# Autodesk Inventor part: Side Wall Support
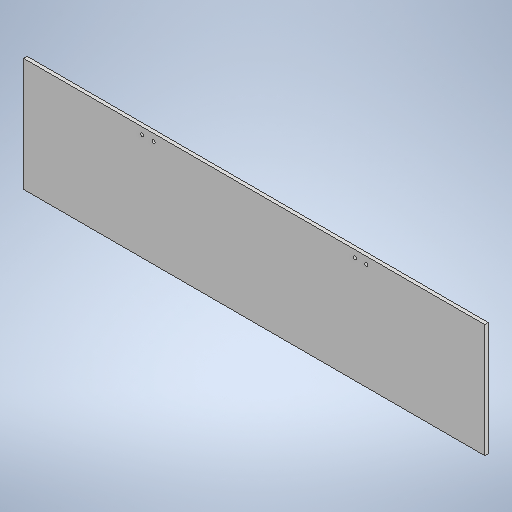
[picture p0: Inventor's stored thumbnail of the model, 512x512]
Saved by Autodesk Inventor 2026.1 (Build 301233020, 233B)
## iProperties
Created: 2026-10
Part Number: Side Wall Support
Material: Generic
Document SubType Name: Modeling
Designer: hp
Density: 1 g/cm^3
Appearance: Default
Author: hp
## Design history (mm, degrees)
sketch "Sketch1"
  geometry: L1 (0, 0)-(700, 0); L2 (700, 160)-(0, 160); L3 (0, 160)-(0, 0); L4 (700, 160)-(700, 0); L5 (50, 160)-(50, 0)
  constraints: 10 end point, 2 point on line, 1 horizontal, 1 parallel, 1 perpendicular, 1 vertical
  dimensions: "d28" = 700 distance of L2.start L2.end; "d29" = 160 distance of L2.end L1.start; "d48" = 50 distance between parallel lines of L3 L5
extrude "Extrusion2" new body sketch "Sketch1" distance "d23" = 5; taper "d24" = 0 deg
sketch "Sketch4"
  geometry: 4 further points
hole "Hole1" sketch "Sketch4" at (217, 150), (233, 150), (517, 150), (533, 150) diameter "d49" = 4.5; stored, may be unused: countersink angle "d53" = 90 deg, drill point angle "d55" = 0 deg; dims "d50" = 6, "d51" = 4, "d52" = 2, "d54" = 8
body "Solid2"
